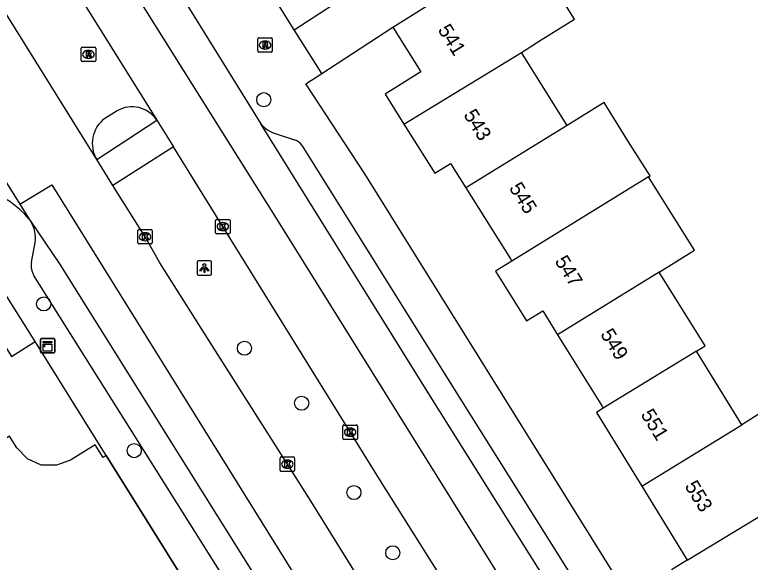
# Model space of a CAD drawing. Extents: x 157767 to 159171, y 387842 to 389425.
# Drawn here: x 158590.6 to 158641.5, y 388186.4 to 388224.4 of the extents above; entities that cross this region are included whole.
import ezdxf

# ---------------------------------------------------------------- set-up
doc = ezdxf.new("R2010")
doc.units = 0
for name, color, linetype in [('IMGEO_Boom', 7, 'Continuous'), ('IMGEO_Kast', 7, 'Continuous'), ('IMGEO_Kolk', 7, 'Continuous'), ('IMGEO_Lichtpunt', 7, 'Continuous'), ('IMGEO_Muur', 7, 'Continuous'), ('IMGEO_Pand', 7, 'Continuous'), ('IMGEO_Pand_nummerreeks', 7, 'Continuous'), ('IMGEO_Rijbaan_lokaal_gesloten', 7, 'Continuous'), ('IMGEO_Rijbaan_lokaal_open', 7, 'Continuous'), ('IMGEO_Rioolput', 7, 'Continuous'), ('IMGEO_Voetpad_open', 7, 'Continuous')]:
    doc.layers.add(name, color=color, linetype=linetype)

msp = doc.modelspace()

# ---------------------------------------------------------------- linework, layer by layer
at = {"layer": 'IMGEO_Boom'}
for centre in [(158607.842, 388218.49), (158592.598, 388204.34), (158606.506, 388201.268), (158610.466, 388197.459), (158598.869, 388194.176), (158614.088, 388191.275), (158616.777, 388187.098)]:
    msp.add_circle(centre, 0.489, dxfattribs=at)
at = {"layer": 'IMGEO_Kast'}
for p, q in [((158592.377, 388201.024), (158592.377, 388201.865)), ((158592.377, 388201.865), (158592.377, 388201.024)), ((158592.452, 388201.949), (158593.293, 388201.949)), ((158593.293, 388201.949), (158592.452, 388201.949)), ((158593.377, 388201.874), (158593.377, 388201.033)), ((158593.377, 388201.033), (158593.377, 388201.874)), ((158593.302, 388200.949), (158592.461, 388200.949)), ((158592.461, 388200.949), (158593.302, 388200.949))]:
    msp.add_line(p, q, dxfattribs=at)
for points in [[(158592.572, 388201.739), (158593.172, 388201.739), (158593.172, 388201.654), (158592.572, 388201.654), (158592.572, 388201.739)], [(158592.572, 388201.564), (158593.172, 388201.564), (158593.172, 388201.075), (158592.572, 388201.075), (158592.572, 388201.564)]]:
    msp.add_lwpolyline(points, dxfattribs=at)
msp.add_circle((158592.656, 388201.413), 0.0377, dxfattribs=at)
for centre, start, end in [((158592.455, 388201.871), 92.4484, 184.2845), ((158592.455, 388201.871), 92.4484, 184.2845), ((158593.299, 388201.871), 2.4484, 94.2845), ((158593.299, 388201.871), 2.4484, 94.2845), ((158592.455, 388201.027), 182.4484, 274.2845), ((158592.455, 388201.027), 182.4484, 274.2845), ((158593.299, 388201.027), 272.4484, 4.2845), ((158593.299, 388201.027), 272.4484, 4.2845)]:
    msp.add_arc(centre, 0.0779, start, end, dxfattribs=at)
at = {"layer": 'IMGEO_Kolk'}
for p, q in [((158604.504, 388209.273), (158604.504, 388210.125)), ((158604.579, 388210.199), (158605.431, 388210.199)), ((158604.992, 388209.979), (158605.017, 388209.979)), ((158605.505, 388210.125), (158605.505, 388209.273)), ((158599.193, 388209.495), (158600.045, 388209.495)), ((158599.118, 388208.569), (158599.118, 388209.421)), ((158599.606, 388209.275), (158599.631, 388209.275)), ((158600.119, 388209.421), (158600.119, 388208.569)), ((158605.431, 388209.199), (158604.579, 388209.199)), ((158605.015, 388209.419), (158604.99, 388209.419)), ((158600.045, 388208.495), (158599.193, 388208.495)), ((158599.629, 388208.715), (158599.604, 388208.715)), ((158613.324, 388195.026), (158613.324, 388195.878)), ((158613.399, 388195.952), (158614.251, 388195.952)), ((158613.812, 388195.732), (158613.837, 388195.732)), ((158614.325, 388195.878), (158614.325, 388195.026)), ((158613.835, 388195.172), (158613.81, 388195.172)), ((158614.251, 388194.952), (158613.399, 388194.952)), ((158608.978, 388192.81), (158608.978, 388193.662)), ((158609.053, 388193.736), (158609.905, 388193.736)), ((158609.979, 388193.662), (158609.979, 388192.81)), ((158609.466, 388193.516), (158609.491, 388193.516)), ((158609.905, 388192.736), (158609.053, 388192.736)), ((158609.489, 388192.956), (158609.464, 388192.956))]:
    msp.add_line(p, q, dxfattribs=at)
for points in [[(158604.504, 388209.273), (158604.504, 388210.125)], [(158604.579, 388210.199), (158605.431, 388210.199)], [(158605.505, 388210.125), (158605.505, 388209.273)], [(158599.193, 388209.495), (158600.045, 388209.495)], [(158604.825, 388209.899), (158604.948, 388209.899), (158604.948, 388209.748), (158605.078, 388209.899), (158605.242, 388209.899), (158605.096, 388209.748), (158605.249, 388209.499), (158605.097, 388209.499), (158605.012, 388209.663), (158604.948, 388209.596), (158604.948, 388209.499), (158604.825, 388209.499), (158604.825, 388209.899)], [(158599.118, 388208.569), (158599.118, 388209.421)], [(158599.439, 388209.195), (158599.562, 388209.195), (158599.562, 388209.044), (158599.692, 388209.195), (158599.856, 388209.195), (158599.71, 388209.044), (158599.863, 388208.795), (158599.711, 388208.795), (158599.626, 388208.959), (158599.562, 388208.892), (158599.562, 388208.795), (158599.439, 388208.795), (158599.439, 388209.195)], [(158600.119, 388209.421), (158600.119, 388208.569)], [(158605.431, 388209.199), (158604.579, 388209.199)], [(158600.045, 388208.495), (158599.193, 388208.495)], [(158613.324, 388195.026), (158613.324, 388195.878)], [(158613.399, 388195.952), (158614.251, 388195.952)], [(158614.325, 388195.878), (158614.325, 388195.026)], [(158613.645, 388195.652), (158613.768, 388195.652), (158613.768, 388195.501), (158613.898, 388195.652), (158614.062, 388195.652), (158613.916, 388195.501), (158614.069, 388195.252), (158613.917, 388195.252), (158613.832, 388195.416), (158613.768, 388195.349), (158613.768, 388195.252), (158613.645, 388195.252), (158613.645, 388195.652)], [(158614.251, 388194.952), (158613.399, 388194.952)], [(158608.978, 388192.81), (158608.978, 388193.662)], [(158609.053, 388193.736), (158609.905, 388193.736)], [(158609.979, 388193.662), (158609.979, 388192.81)], [(158609.299, 388193.436), (158609.422, 388193.436), (158609.422, 388193.285), (158609.552, 388193.436), (158609.716, 388193.436), (158609.57, 388193.285), (158609.723, 388193.036), (158609.571, 388193.036), (158609.486, 388193.2), (158609.422, 388193.133), (158609.422, 388193.036), (158609.299, 388193.036), (158609.299, 388193.436)], [(158609.905, 388192.736), (158609.053, 388192.736)]]:
    msp.add_lwpolyline(points, dxfattribs=at)
for centre, start, end in [((158604.581, 388210.123), 91.552, 178.448), ((158604.581, 388210.123), 91.552, 178.448), ((158605.429, 388210.123), 1.552, 88.448), ((158605.429, 388210.123), 1.552, 88.448), ((158599.195, 388209.419), 91.552, 178.448), ((158599.195, 388209.419), 91.552, 178.448), ((158600.043, 388209.419), 1.552, 88.448), ((158600.043, 388209.419), 1.552, 88.448), ((158604.581, 388209.275), 181.552, 268.448), ((158604.581, 388209.275), 181.552, 268.448), ((158605.429, 388209.275), 271.552, 358.448), ((158605.429, 388209.275), 271.552, 358.448), ((158599.195, 388208.571), 181.552, 268.448), ((158599.195, 388208.571), 181.552, 268.448), ((158600.043, 388208.571), 271.552, 358.448), ((158600.043, 388208.571), 271.552, 358.448), ((158613.401, 388195.876), 91.552, 178.448), ((158613.401, 388195.876), 91.552, 178.448), ((158614.249, 388195.876), 1.552, 88.448), ((158614.249, 388195.876), 1.552, 88.448), ((158613.401, 388195.028), 181.552, 268.448), ((158613.401, 388195.028), 181.552, 268.448), ((158614.249, 388195.028), 271.552, 358.448), ((158614.249, 388195.028), 271.552, 358.448), ((158609.055, 388193.66), 91.552, 178.448), ((158609.055, 388193.66), 91.552, 178.448), ((158609.903, 388193.66), 1.552, 88.448), ((158609.903, 388193.66), 1.552, 88.448), ((158609.055, 388192.812), 181.552, 268.448), ((158609.055, 388192.812), 181.552, 268.448), ((158609.903, 388192.812), 271.552, 358.448), ((158609.903, 388192.812), 271.552, 358.448)]:
    msp.add_arc(centre, 0.0765, start, end, dxfattribs=at)
for centre, major_axis, ratio, start_param, end_param in [((158604.991, 388209.699), (-0.387, 0.002), 0.722429, 4.712389, 7.853982), ((158605.016, 388209.699), (-0.39, 0.002), 0.717154, 1.570796, 4.712389), ((158599.605, 388208.995), (-0.387, 0.002), 0.722429, 4.712389, 7.853982), ((158599.63, 388208.995), (-0.39, 0.002), 0.717154, 1.570796, 4.712389), ((158613.811, 388195.452), (-0.387, 0.002), 0.722429, 4.712389, 7.853982), ((158613.836, 388195.452), (-0.39, 0.002), 0.717154, 1.570796, 4.712389), ((158609.465, 388193.236), (-0.387, 0.002), 0.722429, 4.712389, 7.853982), ((158609.49, 388193.236), (-0.39, 0.002), 0.717154, 1.570796, 4.712389)]:
    msp.add_ellipse(centre, major_axis=major_axis, ratio=ratio, start_param=start_param, end_param=end_param, dxfattribs=at)
at = {"layer": 'IMGEO_Lichtpunt'}
for p, q in [((158603.229, 388207.233), (158603.229, 388206.426)), ((158603.229, 388207.233), (158603.229, 388206.426)), ((158604.131, 388207.328), (158603.323, 388207.328)), ((158604.131, 388207.328), (158603.323, 388207.328)), ((158604.225, 388206.426), (158604.225, 388207.233)), ((158604.225, 388206.426), (158604.225, 388207.233)), ((158603.323, 388206.332), (158604.131, 388206.332)), ((158603.323, 388206.332), (158604.131, 388206.332))]:
    msp.add_line(p, q, dxfattribs=at)
for points in [[(158603.603, 388206.897), (158603.642, 388206.869), (158603.454, 388206.607), (158603.416, 388206.634), (158603.603, 388206.897)], [(158603.815, 388206.869), (158603.853, 388206.896), (158604.04, 388206.634), (158604.001, 388206.606), (158603.815, 388206.869)], [(158603.705, 388206.849), (158603.752, 388206.849), (158603.752, 388206.527), (158603.705, 388206.527), (158603.705, 388206.849)]]:
    msp.add_lwpolyline(points, dxfattribs=at)
msp.add_circle((158603.728, 388207.031), 0.0994, dxfattribs=at)
for centre, start, end in [((158603.323, 388207.233), 90, 180), ((158603.323, 388207.233), 90, 180), ((158604.131, 388207.233), 0, 90), ((158604.131, 388207.233), 0, 90), ((158603.323, 388206.426), 180, 270), ((158603.323, 388206.426), 180, 270), ((158604.131, 388206.426), 270, 0), ((158604.131, 388206.426), 270, 360)]:
    msp.add_arc(centre, 0.0946, start, end, dxfattribs=at)
at = {"layer": 'IMGEO_Muur'}
msp.add_lwpolyline([(158596.931, 388193.835), (158605.271, 388180.491)], dxfattribs=at)
at = {"layer": 'IMGEO_Pand'}
for points in [[(158616.774, 388223.525), (158623.761, 388227.9), (158626.085, 388229.332)], [(158625.706, 388221.754), (158627.059, 388222.632), (158629.373, 388224.081), (158626.085, 388229.332)], [(158616.774, 388223.525), (158618.713, 388220.429), (158616.242, 388218.882), (158617.55, 388216.793)], [(158617.55, 388216.793), (158625.706, 388221.754)], [(158628.869, 388216.702), (158625.706, 388221.754)], [(158634.503, 388213.15), (158634.596, 388213.208), (158633.07, 388215.646), (158631.412, 388218.294), (158628.869, 388216.702)], [(158617.55, 388216.793), (158619.681, 388213.39), (158620.781, 388214.078), (158621.84, 388212.386)], [(158628.869, 388216.702), (158621.84, 388212.386)], [(158634.503, 388213.15), (158625.022, 388207.303)], [(158635.237, 388206.53), (158637.688, 388208.064), (158634.503, 388213.15)], [(158621.84, 388212.386), (158624.925, 388207.458), (158625.022, 388207.303)], [(158625.022, 388207.303), (158623.886, 388206.603), (158626.038, 388203.166), (158627.168, 388203.873), (158628.198, 388202.209)], [(158635.237, 388206.53), (158628.198, 388202.209)], [(158637.825, 388201.077), (158638.422, 388201.444), (158635.237, 388206.53)], [(158583.146, 388201.09), (158588.168, 388204.222), (158590.359, 388200.709), (158591.997, 388201.731)], [(158628.198, 388202.209), (158631.297, 388197.205), (158631.357, 388197.108)], [(158596.931, 388193.835), (158591.997, 388201.731)], [(158637.825, 388201.077), (158631.357, 388197.108)], [(158640.967, 388195.967), (158637.825, 388201.077)], [(158646.133, 388192.02), (158646.723, 388192.383), (158643.53, 388197.582), (158640.967, 388195.967)], [(158631.357, 388197.108), (158630.884, 388196.817), (158634.023, 388191.705)], [(158634.023, 388191.705), (158640.967, 388195.967)], [(158596.931, 388193.835), (158596.713, 388193.699), (158596.163, 388194.581), (158594.466, 388193.523), (158593.476, 388193.165), (158592.434, 388193.175), (158591.475, 388193.615), (158590.744, 388194.373), (158590.236, 388195.187), (158587.824, 388193.682)], [(158634.023, 388191.705), (158637.097, 388186.697), (158637.166, 388186.586)], [(158637.166, 388186.586), (158646.133, 388192.02)], [(158637.166, 388186.586), (158636.079, 388185.927), (158639.217, 388180.813)]]:
    msp.add_lwpolyline(points, dxfattribs=at)
at = {"layer": 'IMGEO_Rijbaan_lokaal_gesloten'}
for points in [[(158634.37, 388169.115), (158623.602, 388186.404), (158608.74, 388210.225), (158593.839, 388234.024), (158572.859, 388267.7)], [(158592.625, 388229.587), (158600.436, 388217.063)], [(158596.27, 388214.348), (158588.442, 388226.901)], [(158602.475, 388225.151), (158607.631, 388216.823)], [(158583.071, 388223.836), (158590.939, 388211.246)], [(158600.436, 388217.063), (158601.582, 388215.216)], [(158633.918, 388174.741), (158629.551, 388181.73), (158619.389, 388197.931), (158607.631, 388216.823)], [(158631.865, 388166.865), (158631.299, 388167.662), (158630.758, 388168.476), (158626.761, 388174.906), (158621.434, 388183.356), (158615.929, 388192.087), (158605.077, 388209.586), (158603.275, 388212.489), (158601.582, 388215.216)], [(158597.392, 388212.554), (158596.27, 388214.348)], [(158590.939, 388211.246), (158593.162, 388212.593), (158602.586, 388197.444), (158620.732, 388168.245), (158626.043, 388159.864)], [(158629.046, 388161.861), (158622.142, 388172.911), (158617.332, 388180.649), (158611.001, 388190.832), (158604.502, 388201.086), (158600.639, 388207.182), (158599.628, 388208.979), (158597.392, 388212.554)], [(158590.939, 388211.246), (158591.586, 388210.211)], [(158591.586, 388210.211), (158591.697, 388210.06)], [(158591.697, 388210.06), (158593.693, 388207.116), (158602.034, 388193.789), (158607.99, 388184.287), (158614.566, 388173.676), (158620.371, 388164.356), (158623.918, 388158.846)]]:
    msp.add_lwpolyline(points, dxfattribs=at)
at = {"layer": 'IMGEO_Rijbaan_lokaal_open'}
msp.add_lwpolyline([(158597.689, 388217.714), (158596.826, 388217.194)], dxfattribs=at)
for centre, radius, start, end in [((158598.727, 388215.971), 2.028, 32.5613, 120.7741), ((158598.134, 388215.461), 2.171, 127.039, 210.8526), ((158587.047, 388206.553), 5.83, 38.87, 109.5542)]:
    msp.add_arc(centre, radius, start, end, dxfattribs=at)
at = {"layer": 'IMGEO_Rioolput'}
for p, q in [((158607.434, 388221.851), (158607.434, 388222.703)), ((158607.509, 388222.777), (158608.361, 388222.777)), ((158608.435, 388222.703), (158608.435, 388221.851)), ((158607.922, 388222.557), (158607.947, 388222.557)), ((158595.198, 388221.203), (158595.198, 388222.055)), ((158595.273, 388222.129), (158596.125, 388222.129)), ((158595.686, 388221.909), (158595.711, 388221.909)), ((158596.199, 388222.055), (158596.199, 388221.203)), ((158608.361, 388221.777), (158607.509, 388221.777)), ((158607.945, 388221.997), (158607.92, 388221.997)), ((158595.709, 388221.349), (158595.684, 388221.349)), ((158596.125, 388221.129), (158595.273, 388221.129))]:
    msp.add_line(p, q, dxfattribs=at)
for points in [[(158607.434, 388221.851), (158607.434, 388222.703)], [(158607.509, 388222.777), (158608.361, 388222.777)], [(158608.435, 388222.703), (158608.435, 388221.851)], [(158608.023, 388222.475), (158607.771, 388222.477), (158607.771, 388222.077)], [(158607.771, 388222.077), (158607.895, 388222.077), (158607.895, 388222.239), (158607.906, 388222.239)], [(158607.949, 388222.396), (158607.895, 388222.396), (158607.895, 388222.315)], [(158607.895, 388222.315), (158607.947, 388222.315)], [(158607.953, 388222.21), (158608.024, 388222.077), (158608.164, 388222.077), (158608.099, 388222.203)], [(158595.198, 388221.203), (158595.198, 388222.055)], [(158595.273, 388222.129), (158596.125, 388222.129)], [(158595.787, 388221.827), (158595.535, 388221.829), (158595.535, 388221.429)], [(158595.713, 388221.748), (158595.659, 388221.748), (158595.659, 388221.667)], [(158595.659, 388221.667), (158595.711, 388221.667)], [(158596.199, 388222.055), (158596.199, 388221.203)], [(158608.361, 388221.777), (158607.509, 388221.777)], [(158595.535, 388221.429), (158595.659, 388221.429), (158595.659, 388221.591), (158595.67, 388221.591)], [(158595.717, 388221.562), (158595.788, 388221.429), (158595.928, 388221.429), (158595.863, 388221.555)], [(158596.125, 388221.129), (158595.273, 388221.129)]]:
    msp.add_lwpolyline(points, dxfattribs=at)
for centre, radius, start, end in [((158607.511, 388222.701), 0.0765, 91.552, 178.448), ((158607.511, 388222.701), 0.0765, 91.552, 178.448), ((158608.359, 388222.701), 0.0765, 1.552, 88.448), ((158608.359, 388222.701), 0.0765, 1.552, 88.448), ((158607.905, 388222.186), 0.0533, 26.0293, 88.6989), ((158607.931, 388222.504), 0.19, 274.7715, 282.9687), ((158607.955, 388222.3), 0.0964, 77.0061, 93.1865), ((158607.969, 388222.357), 0.0378, 276.6634, 79.6772), ((158608.022, 388222.365), 0.109, 350.3612, 89.416), ((158608.02, 388222.365), 0.112, 277.5842, 350.9817), ((158608.004, 388222.15), 0.108, 29.5134, 73.7905), ((158595.275, 388222.053), 0.0765, 91.552, 178.448), ((158595.275, 388222.053), 0.0765, 91.552, 178.448), ((158595.695, 388221.856), 0.19, 274.7715, 282.9687), ((158595.719, 388221.652), 0.0964, 77.0061, 93.1865), ((158595.733, 388221.709), 0.0378, 276.6634, 79.6772), ((158595.786, 388221.717), 0.109, 350.3612, 89.416), ((158595.784, 388221.717), 0.112, 277.5842, 350.9817), ((158596.123, 388222.053), 0.0765, 1.552, 88.448), ((158596.123, 388222.053), 0.0765, 1.552, 88.448), ((158607.511, 388221.853), 0.0765, 181.552, 268.448), ((158607.511, 388221.853), 0.0765, 181.552, 268.448), ((158608.359, 388221.853), 0.0765, 271.552, 358.448), ((158608.359, 388221.853), 0.0765, 271.552, 358.448), ((158595.275, 388221.205), 0.0765, 181.552, 268.448), ((158595.275, 388221.205), 0.0765, 181.552, 268.448), ((158595.669, 388221.538), 0.0533, 26.0293, 88.6989), ((158595.768, 388221.502), 0.108, 29.5134, 73.7905), ((158596.123, 388221.205), 0.0765, 271.552, 358.448), ((158596.123, 388221.205), 0.0765, 271.552, 358.448)]:
    msp.add_arc(centre, radius, start, end, dxfattribs=at)
for centre, major_axis, ratio, start_param, end_param in [((158607.921, 388222.277), (-0.387, 0.002), 0.722429, 4.712389, 7.853982), ((158607.946, 388222.277), (-0.39, 0.002), 0.717154, 1.570796, 4.712389), ((158595.685, 388221.629), (-0.387, 0.002), 0.722429, 4.712389, 7.853982), ((158595.71, 388221.629), (-0.39, 0.002), 0.717154, 1.570796, 4.712389)]:
    msp.add_ellipse(centre, major_axis=major_axis, ratio=ratio, start_param=start_param, end_param=end_param, dxfattribs=at)
at = {"layer": 'IMGEO_Voetpad_open'}
for points in [[(158609.939, 388223.32), (158593.8, 388249.118)], [(158609.939, 388223.32), (158615.354, 388226.863)], [(158611.857, 388220.315), (158609.939, 388223.32)], [(158611.857, 388220.315), (158616.774, 388223.525)], [(158638.306, 388175.676), (158614.837, 388213.345), (158610.758, 388219.597), (158611.857, 388220.315)], [(158596.27, 388214.348), (158600.436, 388217.063)], [(158608.631, 388216.154), (158609.981, 388215.704)], [(158601.582, 388215.216), (158597.392, 388212.554)], [(158610.513, 388215.284), (158620.79, 388198.807), (158630.951, 388182.607), (158636.566, 388173.621)], [(158591.746, 388207.234), (158591.997, 388208.589)], [(158622.071, 388158.27), (158613.03, 388172.75), (158591.923, 388206.308)], [(158591.997, 388201.731), (158589.589, 388205.583)], [(158605.271, 388180.491), (158596.931, 388193.835)]]:
    msp.add_lwpolyline(points, dxfattribs=at)
for centre, radius, start, end in [((158609.275, 388218.199), 2.144, 219.9239, 252.511), ((158609.656, 388214.745), 1.012, 32.1516, 71.2681), ((158590.028, 388208.954), 2.003, 349.5121, 33.5419), ((158593.015, 388206.997), 1.291, 169.4055, 212.237)]:
    msp.add_arc(centre, radius, start, end, dxfattribs=at)

# ---------------------------------------------------------------- texts
at = {"layer": 'IMGEO_Pand_nummerreeks'}
for s, rotation, p in [('541', 302.0586, (158619.868, 388223.332)), ('543', 301.9519, (158621.645, 388217.442)), ('545', 301.9536, (158624.805, 388212.375)), ('547', 301.9536, (158627.965, 388207.308)), ('549', 301.9536, (158631.126, 388202.241)), ('551', 301.5468, (158633.923, 388196.683)), ('553', 301.5468, (158636.969, 388191.72))]:
    msp.add_text(s, height=1, rotation=rotation, dxfattribs=at).set_placement(p)

doc.saveas('drawing.dxf')
